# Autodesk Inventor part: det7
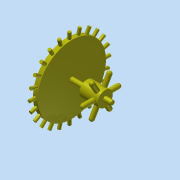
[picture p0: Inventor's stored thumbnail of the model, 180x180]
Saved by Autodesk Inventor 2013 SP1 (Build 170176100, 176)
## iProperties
Created: 2016-04
Part Number: det7
Material: Пластик АБС
Document SubType Name: Modeling
Designer: Кравец
Density: 1 g/cm^3
Author: Кравец
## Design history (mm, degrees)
sketch "Эскиз1"
  geometry: L1 (-2.986, 0)-(27.014, 0); L2 (27.014, 0)-(27.014, 22.5); L3 (27.014, 22.5)-(24.014, 22.5); L4 (24.014, 22.5)-(24.014, 1.5); L5 (24.014, 1.5)-(14.014, 1.5); L6 (14.014, 1.5)-(14.014, 5); L7 (14.014, 5)-(2.014, 5); L8 (2.014, 5)-(2.014, 1.5); L9 (2.014, 1.5)-(-2.986, 1.5); L10 (-2.986, 1.5)-(-2.986, 0); 1 further point
  constraints: 21 end point, 6 parallel, 3 perpendicular, 1 collinear, 1 horizontal
  dimensions: "d0" = 5 distance of L8.end L9.end; "d2" = 10 distance of L4.end L5.end; "d3" = 12 distance of L6.end L7.end; "d4" = 3 distance of L2.end L3.end; "d5" = 10 diameter of L7 L1; "d6" = 3 diameter of L9 L1; "d7" = 45 diameter of L3 L1
revolve "Вращение1" sketch "Эскиз1" stored, may be unused: angle "d8" = 90 deg
node "РабПлоскость1"
sketch "Эскиз2"
  geometry: L1 (1.5, -22.5)-(1.5, 22.5) reference; L2 (1.5, 0)-(4.397, 0); C1 r 1 at (0, 0); 1 further point
  constraints: 2 end point, 1 centre point, 1 midpoint, 1 perpendicular, 1 point on line
  dimensions: "d9" = 2 diameter of C1; "d11" = 1.5 distance from line of C1.centre L1
extrude "Выдавливание1" join sketch "Эскиз2" distance "d12" = 4; taper "d14" = 0 deg; dims "d13" = 2, "d15" = 0
node "РабПлоскость2"
sketch "Эскиз3"
  geometry: L1 (-8.014, 0)-(-3, 0); C1 r 1.5 at (-3, 0); 2 further points; 1 other entity
  constraints: 2 end point, 1 centre point, 1 horizontal, 2 other
  dimensions: "d19" = 3 diameter of C1; "d21" = 3 dimension on L1.end
extrude "Выдавливание2" join sketch "Эскиз3" distance "d22" = 8; taper "d24" = 0 deg; dims "d23" = 2, "d25" = 0
fillet "Сопряжение1" dims "d26" = 1.5
pattern_circular "Круговой массив2" dims angle "d28" = 360 deg
fillet "Сопряжение2" dims "d30" = 0.5
node "Твердое тело1"
pattern_circular "Круговой массив1" dims angle "d17" = 360 deg
